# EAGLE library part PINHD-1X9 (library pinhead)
PIN HEADER
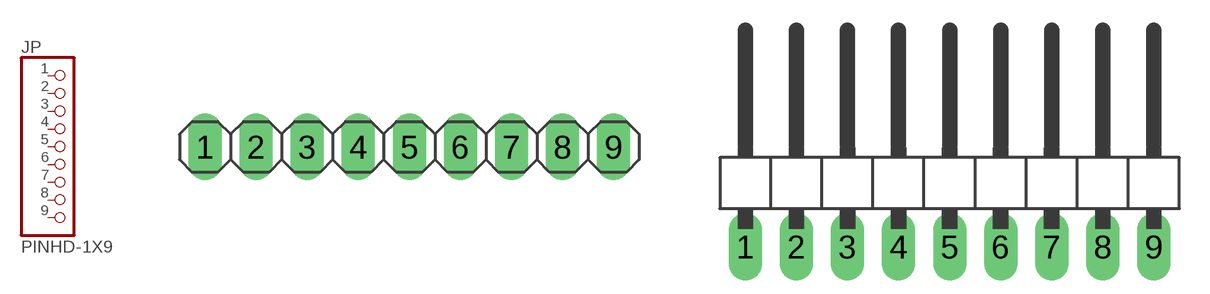
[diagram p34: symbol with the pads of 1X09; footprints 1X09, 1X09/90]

Designator prefix JP

## PINHD-1X9  [1X09]
1  1  pas
2  2  pas
3  3  pas
4  4  pas
5  5  pas
6  6  pas
7  7  pas
8  8  pas
9  9  pas

## PINHD-1X9/90  [1X09/90]
Pads as for 1X09

## Footprint 1X09 (pad centres in mm)
PIN HEADER
drill 1.016 pad 1.67 long: 1 -10.16,0; 2 -7.62,0; 3 -5.08,0; 4 -2.54,0; 5 0,0; 6 2.54,0; 7 5.08,0; 8 7.62,0; 9 10.16,0

## Footprint 1X09/90 (pad centres in mm)
PIN HEADER
drill 1.016 pad 1.67 long: 1 -10.16,-3.81; 2 -7.62,-3.81; 3 -5.08,-3.81; 4 -2.54,-3.81; 5 0,-3.81; 6 2.54,-3.81; 7 5.08,-3.81; 8 7.62,-3.81; 9 10.16,-3.81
